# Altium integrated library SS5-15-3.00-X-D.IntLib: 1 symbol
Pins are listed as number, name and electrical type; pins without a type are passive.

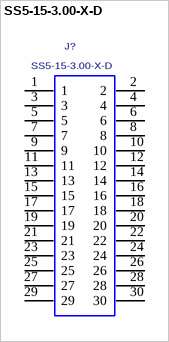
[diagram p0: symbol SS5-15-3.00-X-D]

## SS5-15-3.00-X-D
designator J?
0.5MM SOCKET STRIP ASSEMBLY, 30 PINS.; MANUFACTURER: SAMTEC
footprint SS5-15-3.00-X-D
pins: 1, 2, 3, 4, 5, 6, 7, 8, 9, 10, 11, 12, 13, 14, 15, 16, 17, 18, 19, 20, 21, 22, 23, 24, 25, 26, 27, 28, 29, 30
